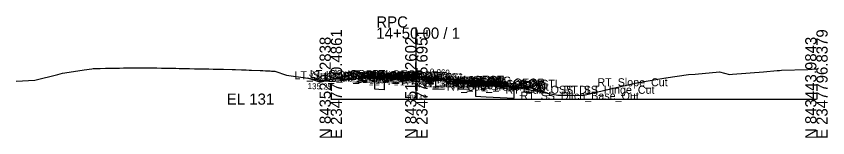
# Model space of a CAD drawing. Extents: x -26 to 203, y -10 to 7538.
# Drawn here: x 0 to 202.8, y 990.3 to 1020.8 of the extents above; entities that cross this region are included whole.
import ezdxf

# ---------------------------------------------------------------- set-up
doc = ezdxf.new("R2010")
doc.units = 0
for name, color, linetype in [('Default', 7, 'Continuous'), ('Exist CMT Pavement', 7, 'Continuous'), ('Exist Cross Section Cell', 7, 'Continuous'), ('Exist XS Center Line Elevation Label', 7, 'Continuous'), ('Exist XS Ground Line', 7, 'Continuous'), ('Prop CMT Pvmt Course 1', 7, 'Continuous'), ('Prop CMT Pvmt Course 1 Wedge', 7, 'Continuous'), ('Prop CMT Pvmt Course 2', 7, 'Continuous'), ('Prop CMT Pvmt Course 2 Wedge', 7, 'Continuous'), ('Prop CMT Pvmt Course 3', 7, 'Continuous'), ('Prop CMT Pvmt Course 3 Wedge', 7, 'Continuous'), ('Prop CMT Pvmt Surface', 7, 'Continuous'), ('Prop CMT Pvmt Surface Shoulder', 7, 'Continuous'), ('Prop CMT Pvmt Wedge Surface 1', 7, 'Continuous'), ('Prop CMT Pvmt Wedge Surface 2', 7, 'Continuous'), ('Prop CMT Pvmt Wedge Surface 3', 7, 'Continuous'), ('Prop CMT Shld Paved Course 1', 7, 'Continuous'), ('Prop CMT Shld Paved Course 2', 7, 'Continuous'), ('Prop CMT Shld Paved Course 3', 7, 'Continuous'), ('Prop CMT Slope Grass', 7, 'Continuous'), ('Prop CMT Subgrade Earthwork', 7, 'Continuous'), ('Prop Road Sect_ Recs - UC (Outline)', 7, 'Continuous'), ('Prop Road Sect_ Recs - UEA (pattern)', 7, 'Continuous'), ('Prop XS Ditch Standard Text', 7, 'Continuous'), ('Prop XS Earthwork Shape', 7, 'Continuous'), ('Prop XS SE Text', 7, 'Continuous'), ('Prop XS Side Slope Text', 7, 'Continuous'), ('Scratch_Level_0', 7, 'Continuous')]:
    doc.layers.add(name, color=color, linetype=linetype)

msp = doc.modelspace()

# ---------------------------------------------------------------- linework, layer by layer
at = {"layer": 'Exist CMT Pavement'}
for q in [(96, 1005.78), (111.31, 1004.63)]:
    msp.add_line((100, 1005.49), q, dxfattribs=at)
at = {"layer": 'Exist Cross Section Cell'}
for p, q in [((100, 1000), (100, 1017.92)), ((78.62, 1000), (100, 1000)), ((100, 1000), (200, 1000))]:
    msp.add_line(p, q, dxfattribs=at)
at = {"layer": 'Exist XS Ground Line'}
msp.add_lwpolyline([(0, 1004.5), (4.62, 1004.73), (10.37, 1006.17), (11.53, 1006.47), (14.32, 1006.91), (16.98, 1007.32), (18.9, 1007.62), (19.24, 1007.63), (20.32, 1007.67), (21.01, 1007.69), (22.3, 1007.71), (22.79, 1007.72), (23.28, 1007.73), (25.83, 1007.78), (26.8, 1007.79), (29.81, 1007.83), (30.15, 1007.83), (32.78, 1007.82), (33.35, 1007.81), (33.92, 1007.81), (35.12, 1007.8), (36.28, 1007.78), (37.52, 1007.75), (38.67, 1007.73), (39.86, 1007.71), (40.73, 1007.69), (42.41, 1007.63), (43.34, 1007.63), (44.57, 1007.61), (45.71, 1007.59), (46.85, 1007.57), (48.16, 1007.55), (49.26, 1007.52), (50.4, 1007.5), (51.11, 1007.48), (51.78, 1007.46), (53.97, 1007.41), (54.82, 1007.38), (56.32, 1007.33), (57.44, 1007.29), (58.18, 1007.26), (58.83, 1007.23), (60.97, 1007.15), (61.64, 1007.13), (62.33, 1007.09), (63.44, 1007.04), (63.81, 1007.01), (64.62, 1006.98), (67.59, 1006.02), (78.91, 1004.37), (91.08, 1005.84), (91.92, 1005.94), (92.71, 1005.94), (94.46, 1005.87), (95.37, 1005.83), (96.46, 1005.74), (97.01, 1005.7), (97.97, 1005.64), (98.78, 1005.58), (99.58, 1005.52), (100, 1005.49), (100.55, 1005.44), (101.53, 1005.37), (102.33, 1005.31), (103.12, 1005.25), (105.12, 1005.1), (106.65, 1004.98), (108.64, 1004.82), (110.11, 1004.69), (111.31, 1004.63), (112.3, 1004.53), (113.6, 1004.44), (114.79, 1004.35), (117.21, 1004.06), (120.44, 1003.67), (121.84, 1003.51), (125.32, 1002.92), (135.34, 1001.02), (138.37, 1001), (141.56, 1000.87), (148.57, 1002.61), (155.43, 1004.18), (162.35, 1005.29), (168.01, 1006.16), (169.66, 1006.27), (175.79, 1006.83), (178.29, 1006.17), (179.04, 1006.23), (186.76, 1006.87), (190.23, 1007.15), (190.79, 1007.2), (191.26, 1007.22), (197.86, 1007.43), (200, 1007.55)], dxfattribs=at)
at = {"layer": 'Prop CMT Pvmt Course 1'}
for p, q in [((100, 1005.66), (96, 1005.94)), ((96, 1005.94), (96, 1005.69)), ((96, 1005.69), (96, 1005.81)), ((96, 1005.81), (100, 1005.54)), ((96, 1005.69), (96, 1005.69)), ((100, 1005.41), (100, 1005.66)), ((100, 1005.66), (112, 1004.83)), ((100, 1005.41), (100, 1005.66)), ((100, 1005.54), (100, 1005.41)), ((111.31, 1004.76), (100, 1005.54)), ((100, 1005.54), (100, 1005.41)), ((100, 1005.41), (100, 1005.41)), ((100, 1005.41), (100, 1005.41)), ((111.31, 1004.63), (111.31, 1004.76)), ((112, 1004.58), (111.31, 1004.63)), ((112, 1004.83), (112, 1004.58))]:
    msp.add_line(p, q, dxfattribs=at)
at = {"layer": 'Prop CMT Pvmt Course 1 Wedge'}
for q in [(96, 1005.81), (111.31, 1004.76)]:
    msp.add_line((100, 1005.54), q, dxfattribs=at)
at = {"layer": 'Prop CMT Pvmt Course 2'}
for p, q in [((96, 1005.35), (96, 1005.69)), ((96, 1005.69), (96, 1005.69)), ((96, 1005.69), (96, 1005.35)), ((96, 1005.35), (96, 1005.35)), ((111.31, 1004.3), (111.31, 1004.63)), ((111.31, 1004.63), (112, 1004.58)), ((112, 1004.25), (111.31, 1004.3)), ((112, 1004.58), (112, 1004.25))]:
    msp.add_line(p, q, dxfattribs=at)
at = {"layer": 'Prop CMT Pvmt Course 2 Wedge'}
for q in [(96, 1005.69), (111.31, 1004.63)]:
    msp.add_line((100, 1005.41), q, dxfattribs=at)
at = {"layer": 'Prop CMT Pvmt Course 3'}
for p, q in [((96, 1005.35), (96, 1005.35)), ((96, 1005.35), (96, 1005.02)), ((96, 1005.02), (96, 1005.35)), ((96, 1005.02), (96, 1005.02)), ((111.31, 1004.3), (112, 1004.25)), ((111.31, 1003.97), (111.31, 1004.3)), ((112, 1004.25), (112, 1003.92)), ((112, 1003.92), (111.31, 1003.97))]:
    msp.add_line(p, q, dxfattribs=at)
at = {"layer": 'Prop CMT Pvmt Course 3 Wedge'}
for q in [(96, 1005.35), (111.31, 1004.3)]:
    msp.add_line((100, 1005.08), q, dxfattribs=at)
at = {"layer": 'Prop CMT Pvmt Surface'}
for q in [(96, 1005.94), (112, 1004.83)]:
    msp.add_line((100, 1005.66), q, dxfattribs=at)
at = {"layer": 'Prop CMT Pvmt Surface Shoulder'}
for p, q in [((96, 1005.94), (92, 1006.21)), ((112, 1004.83), (122, 1004.15))]:
    msp.add_line(p, q, dxfattribs=at)
at = {"layer": 'Prop CMT Pvmt Wedge Surface 1'}
for p, q in [((96, 1005.69), (96, 1005.94)), ((100, 1005.54), (96, 1005.81)), ((96, 1005.81), (96, 1005.69)), ((96, 1005.69), (96, 1005.69)), ((100, 1005.54), (111.31, 1004.76)), ((111.31, 1004.76), (111.31, 1004.63)), ((111.31, 1004.63), (112, 1004.58)), ((112, 1004.58), (112, 1004.83))]:
    msp.add_line(p, q, dxfattribs=at)
at = {"layer": 'Prop CMT Pvmt Wedge Surface 2'}
for p, q in [((96, 1005.69), (96, 1005.94)), ((100, 1005.41), (96, 1005.69)), ((100, 1005.41), (112, 1004.58)), ((112, 1004.58), (112, 1004.83))]:
    msp.add_line(p, q, dxfattribs=at)
at = {"layer": 'Prop CMT Pvmt Wedge Surface 3'}
for p, q in [((96, 1005.35), (96, 1005.94)), ((100, 1005.08), (96, 1005.35)), ((100, 1005.08), (112, 1004.25)), ((112, 1004.25), (112, 1004.83))]:
    msp.add_line(p, q, dxfattribs=at)
at = {"layer": 'Prop CMT Shld Paved Course 1'}
for p, q in [((92, 1006.21), (91.77, 1005.98)), ((96, 1005.94), (92, 1006.21)), ((91.77, 1005.98), (96, 1005.69)), ((96, 1005.69), (96, 1005.94)), ((112, 1004.83), (122, 1004.15)), ((112, 1004.58), (112, 1004.83)), ((122.27, 1003.88), (112, 1004.58)), ((122, 1004.15), (122.27, 1003.88))]:
    msp.add_line(p, q, dxfattribs=at)
at = {"layer": 'Prop CMT Shld Paved Course 2'}
for p, q in [((91.77, 1005.98), (91.45, 1005.67)), ((91.45, 1005.67), (96, 1005.35)), ((96, 1005.69), (91.77, 1005.98)), ((96, 1005.35), (96, 1005.69)), ((112, 1004.58), (122.27, 1003.88)), ((112, 1004.25), (112, 1004.58)), ((122.63, 1003.52), (112, 1004.25)), ((122.27, 1003.88), (122.63, 1003.52))]:
    msp.add_line(p, q, dxfattribs=at)
at = {"layer": 'Prop CMT Shld Paved Course 3'}
for p, q in [((90.95, 1005.7), (90.64, 1005.39)), ((90.64, 1005.39), (96, 1005.02)), ((91.45, 1005.67), (90.95, 1005.7)), ((96, 1005.35), (91.45, 1005.67)), ((96, 1005.02), (96, 1005.35)), ((112, 1004.25), (122.63, 1003.52)), ((112, 1003.92), (112, 1004.25)), ((123.48, 1003.13), (112, 1003.92)), ((122.63, 1003.52), (123.13, 1003.48)), ((123.13, 1003.48), (123.48, 1003.13))]:
    msp.add_line(p, q, dxfattribs=at)
at = {"layer": 'Prop CMT Slope Grass'}
for p, q in [((75.88, 1004.25), (84, 1006.28)), ((92, 1006.21), (84, 1006.28)), ((75.88, 1004.25), (72.89, 1005.25)), ((122, 1004.15), (126, 1003.76)), ((126, 1003.76), (132.75, 1001.51))]:
    msp.add_line(p, q, dxfattribs=at)
at = {"layer": 'Prop CMT Subgrade Earthwork'}
for p, q in [((90.64, 1005.39), (82.63, 1005.94)), ((96, 1005.02), (90.64, 1005.39)), ((96, 1005.02), (96, 1005.78)), ((96, 1005.02), (96, 1005.02)), ((111.31, 1003.97), (111.31, 1004.63)), ((111.31, 1003.97), (112, 1003.92)), ((112, 1003.92), (123.48, 1003.13)), ((123.48, 1003.13), (129.05, 1002.74))]:
    msp.add_line(p, q, dxfattribs=at)
at = {"layer": 'Prop Road Sect_ Recs - UC (Outline)'}
for points in [[(92, 1005.29), (92, 1002.29), (90.64, 1002.39), (89.64, 1002.46), (89.64, 1005.46)], [(114.8, 1003.72), (114.8, 1000.72), (117.48, 1000.54), (124.46, 1000.26), (124.45, 1003.05)]]:
    msp.add_lwpolyline(points, close=True, dxfattribs=at)
at = {"layer": 'Prop Road Sect_ Recs - UEA (pattern)'}
for p, q in [((114.13, 1004.44), (112, 1004.58)), ((112, 1004.58), (112, 1004.56)), ((112, 1004.56), (112.3, 1004.53)), ((112.3, 1004.53), (113.6, 1004.44)), ((116.39, 1004.17), (114.13, 1004.44)), ((116.4, 1004.16), (116.39, 1004.17))]:
    msp.add_line(p, q, dxfattribs=at)
msp.add_lwpolyline([(113.6, 1004.44), (114.79, 1004.35), (116.4, 1004.16)], dxfattribs=at)
at = {"layer": 'Prop XS Earthwork Shape'}
for points in [[(75.88, 1004.25), (72.89, 1005.25), (77.29, 1004.61)], [(88.56, 1005.53), (82.63, 1005.94), (77.29, 1004.61), (78.91, 1004.37)], [(96, 1005.02), (90.64, 1005.39), (88.56, 1005.53), (91.08, 1005.84), (91.92, 1005.94), (92.71, 1005.94), (94.46, 1005.87), (95.37, 1005.83), (96, 1005.78)], [(98.07, 1005.63), (96, 1005.78), (96.46, 1005.74), (97.01, 1005.7), (97.97, 1005.64)], [(98.07, 1005.63), (98.78, 1005.58), (99.58, 1005.52), (100, 1005.49)], [(100, 1005.49), (101.33, 1005.38), (100.55, 1005.44)], [(101.33, 1005.38), (101.59, 1005.37), (101.53, 1005.37)], [(101.59, 1005.37), (102.5, 1005.3), (102.33, 1005.31)], [(102.5, 1005.3), (106.46, 1005), (105.12, 1005.1), (103.12, 1005.25)], [(106.46, 1005), (111.31, 1004.63), (110.11, 1004.69), (108.64, 1004.82), (106.65, 1004.98)], [(111.31, 1003.97), (111.31, 1004.63), (112.3, 1004.53), (113.6, 1004.44), (114.79, 1004.35), (117.21, 1004.06), (120.44, 1003.67), (121.84, 1003.51), (124.49, 1003.06), (123.48, 1003.13), (112, 1003.92)], [(124.49, 1003.06), (125.32, 1002.92), (132.75, 1001.51), (129.05, 1002.74)]]:
    msp.add_lwpolyline(points, close=True, dxfattribs=at)

# ---------------------------------------------------------------- texts
at = {"layer": 'Default'}
msp.add_text('-', height=0.0001, dxfattribs=at).set_placement((78.62, 1000))
at = {"layer": 'Exist Cross Section Cell'}
for s, p in [('RPC', (90, 1017.92)), ('14+50.00 / 1', (90, 1015.12)), ('EL 131', (52.62, 998.6))]:
    msp.add_text(s, height=2.8, dxfattribs=at).set_placement(p)
for s, p in [('E 2347710.4861', (81.42, 990)), ('E 2347725.6951', (102.8, 990)), ('E 2347796.8379', (202.8, 990)), ('N 843529.2838', (78.62, 990)), ('N 843514.2602', (100, 990)), ('N 843443.9843', (200, 990))]:
    msp.add_text(s, height=2.8, rotation=90, dxfattribs=at).set_placement(p)
at = {"layer": 'Exist XS Center Line Elevation Label'}
msp.add_text('136.49', height=1.2, dxfattribs=at).set_placement((97.52, 999.89))
at = {"layer": 'Prop XS Ditch Standard Text'}
msp.add_text('135.25', height=1.5, rotation=358.5679, dxfattribs=at).set_placement((72.8, 1002.52))
at = {"layer": 'Prop XS SE Text'}
for s, rotation, p in [('0.069', 356.0603, (103.3, 1006.18)), ('3:1', 341.5651, (128.48, 1003.71))]:
    msp.add_text(s, height=1.5, rotation=rotation, dxfattribs=at).set_placement(p)
at = {"layer": 'Prop XS Side Slope Text'}
for s, rotation, p in [('3:1', 339.8789, (73.06, 1005.85)), ('4:1', 18.7112, (78.21, 1005.23))]:
    msp.add_text(s, height=1.5, rotation=rotation, dxfattribs=at).set_placement(p)
at = {"layer": 'Scratch_Level_0'}
for s, p in [('LT_Sub_OSS_DLT', (69.55, 1004.97)), ('LT_GS_OS_CTL', (73.37, 1005.28)), ('LT_Sub_Trench_Out', (74.85, 1004.39)), ('LT_PS3_Shelf_Out', (76.94, 1004.7)), ('LT_PV_Sub_Tie_Out', (80.95, 1004.78)), ('LT_PS3_OEOP', (81.69, 1004.67)), ('LT_PS2_OEOP', (82, 1004.98)), ('LT_PS1_OEOP', (82.8, 1005.21)), ('LT_PV_OEEOP_EG', (83.54, 1004.78)), ('LT_Sub_OEEOP', (85.21, 1004.02)), ('LT_PV2_OEEOP', (85.31, 1004.69)), ('LT_PV3_OEEOP', (85.31, 1004.35)), ('LT_PV1_OEEOP', (85.87, 1004.81)), ('LT_Sub_OEOT', (86.08, 1004.02)), ('LT_PV2_OEOT', (86.17, 1004.69)), ('LT_PV3_OEOT', (86.17, 1004.35)), ('LT_PV1_OEOT', (86.74, 1004.94)), ('RT_PV_IEEOP_EG', (88.14, 1004.49)), ('LT_PV_IEEOP_EG', (88.19, 1004.49)), ('RT_PV2_IEEOP', (89.91, 1004.41)), ('RT_PV3_IEEOP', (89.91, 1004.08)), ('LT_PV2_IEEOP', (89.95, 1004.41)), ('LT_PV3_IEEOP', (89.95, 1004.08)), ('RT_PV1_IEEOP', (90.47, 1004.54)), ('LT_PV1_IEEOP', (90.52, 1004.54)), ('PV2_PGL', (93.91, 1004.41)), ('PV1_PGL', (94.47, 1004.66)), ('RT_PV_Sub_Tie_Out', (96.21, 1003.63)), ('RT_PV_OEEOP_EG', (98.8, 1003.63)), ('RT_Sub_OEEOP', (100.47, 1002.97)), ('RT_PV2_OEEOP', (100.57, 1003.63)), ('RT_PV3_OEEOP', (100.57, 1003.3)), ('RT_PV1_OEEOP', (101.14, 1003.76)), ('RT_Sub_OEOT', (102.03, 1002.92)), ('RT_PV2_OEOT', (102.13, 1003.58)), ('RT_PV3_OEOT', (102.13, 1003.25)), ('RT_PV1_OEOT', (102.69, 1003.83)), ('RT_Sub_Trench_Out', (107.64, 1002.13)), ('RT_PS3_Shelf_Out', (109.06, 1002.48)), ('RT_PS2_OEOP', (112.46, 1002.88)), ('RT_PS1_OEOP', (112.76, 1003.15)), ('RT_PS3_OEOP', (112.82, 1002.52)), ('RT_GS_OS_CTL', (115.32, 1002.83)), ('RT_Slope_Cut', (145.28, 1003.22)), ('RT_Sub_OSS_DLT', (122.27, 1001.34)), ('RT_SS_Hinge_Cut', (136.79, 1001.33)), ('RT_SS_Ditch_Base_Out', (126.03, 999.83))]:
    msp.add_text(s, height=2, dxfattribs=at).set_placement(p)

doc.saveas('drawing.dxf')
